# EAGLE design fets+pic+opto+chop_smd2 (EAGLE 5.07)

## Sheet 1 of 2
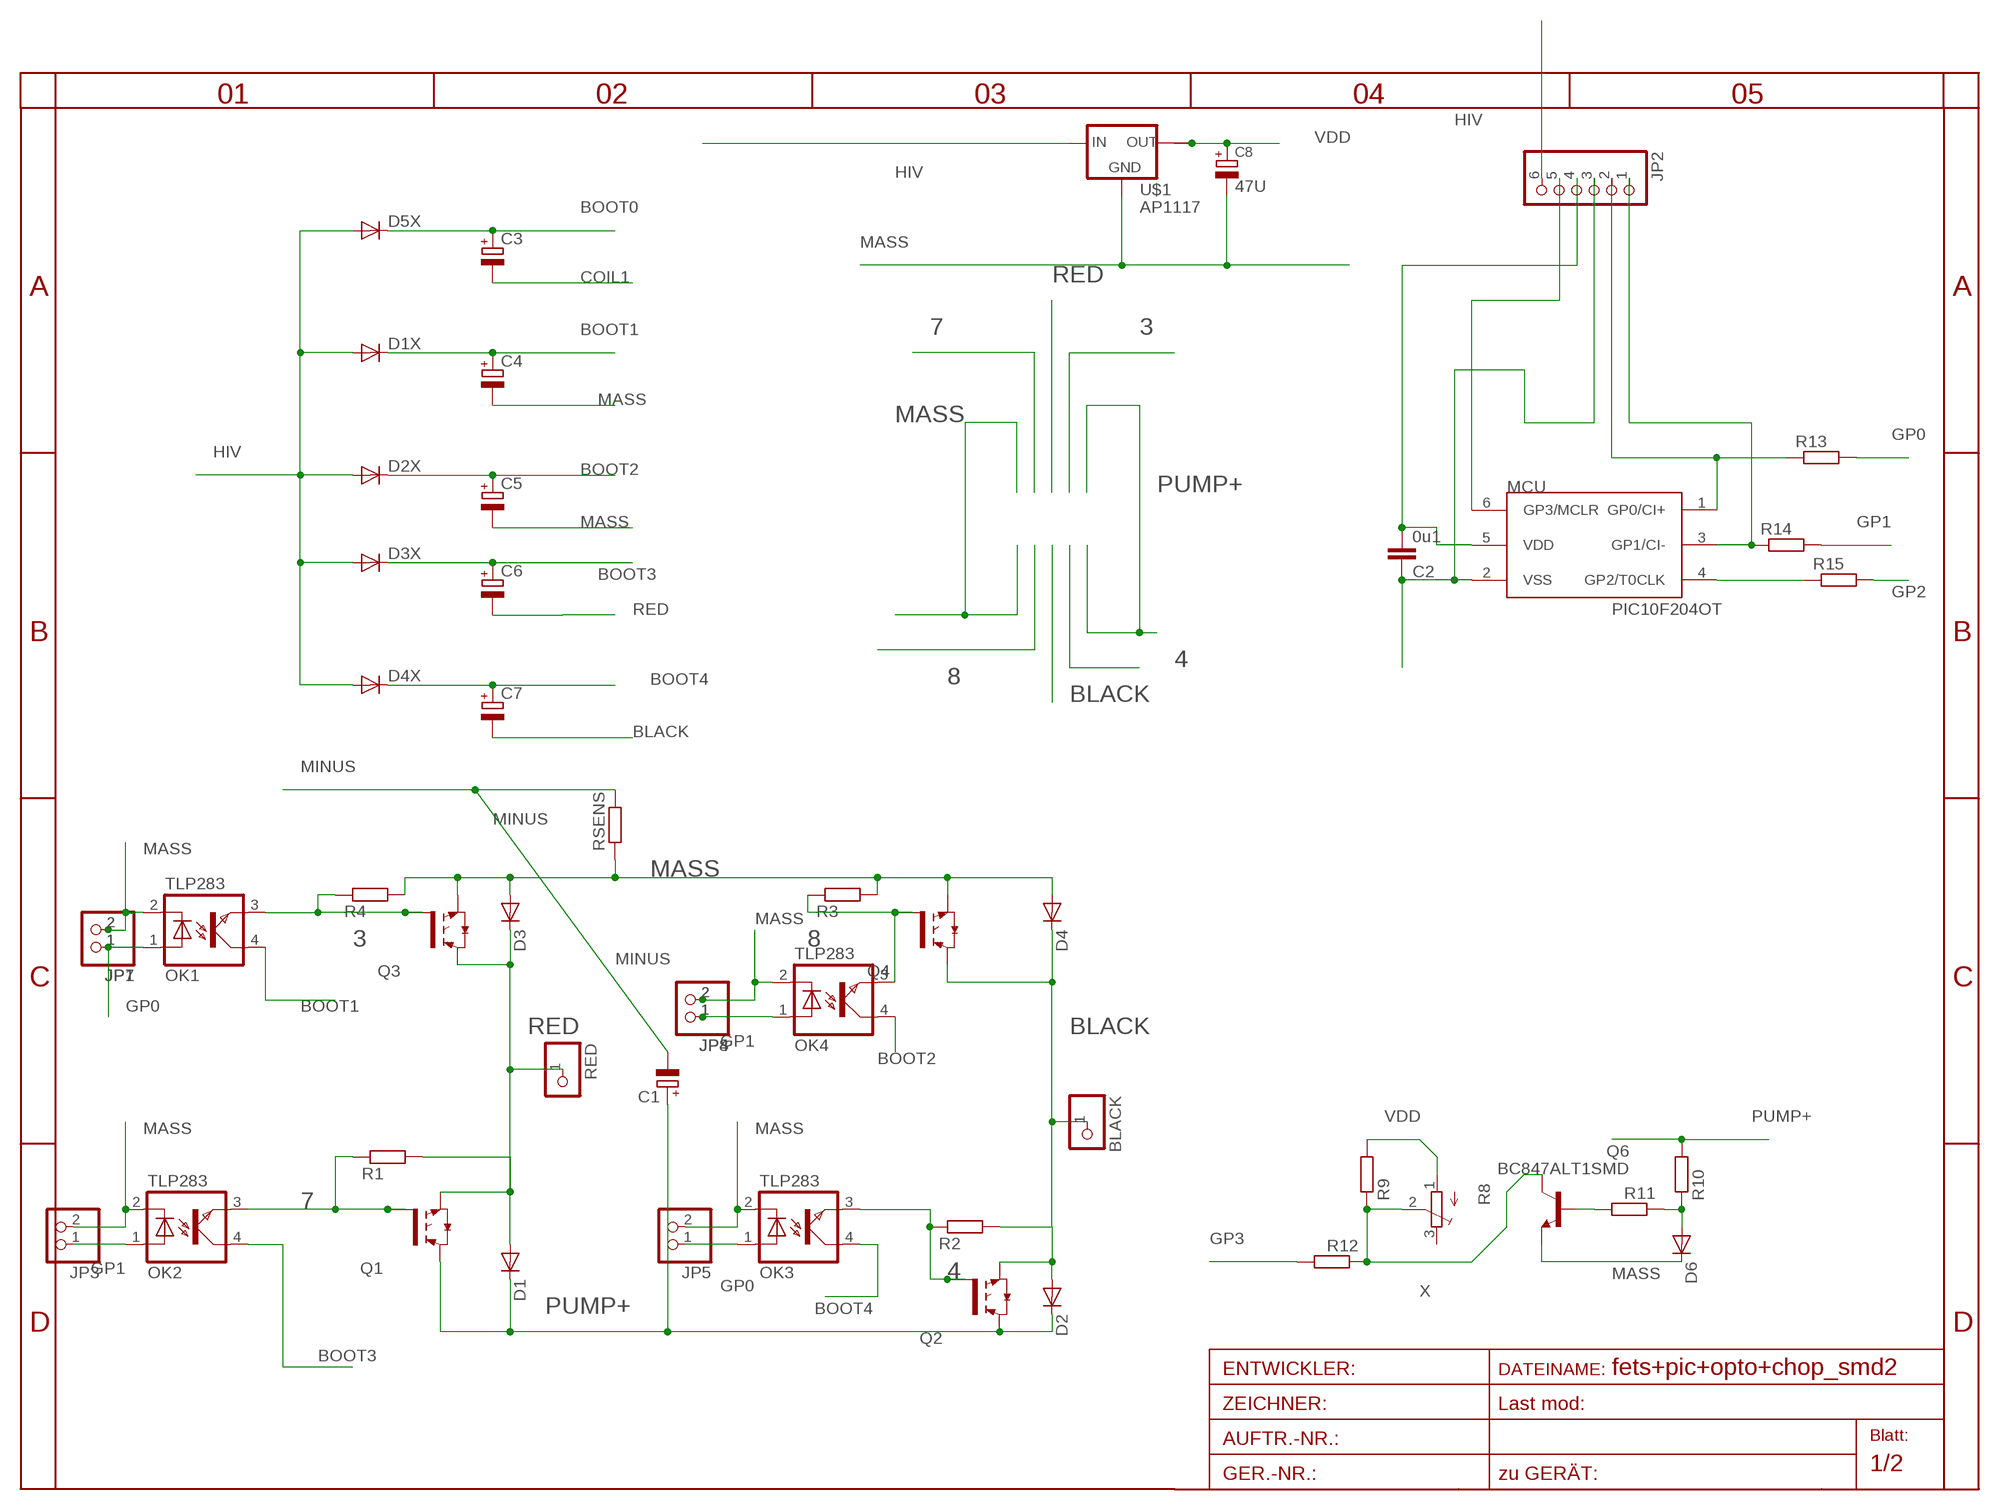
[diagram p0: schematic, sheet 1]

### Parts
BLACK  PINHD-1X14.5MM  [1X4MM5]
C1  CPOL-EUE5-13  [E5-13]
C2  0u1  C-EUC0805  [C0805]
C3  CPOL-EUC  [PANASONIC_C]
C4  CPOL-EUC  [PANASONIC_C]
C5  CPOL-EUC  [PANASONIC_C]
C6  CPOL-EUC  [PANASONIC_C]
C7  CPOL-EUC  [PANASONIC_C]
C8  47U  CPOL-EUC  [PANASONIC_C]
D1  DIODE-SMC  [SMC]
D1X  DIODE-SMA-DO214  [SMA-DO214AC]
D2  DIODE-SMC  [SMC]
D2X  DIODE-SMA-DO214  [SMA-DO214AC]
D3  DIODE-SMC  [SMC]
D3X  DIODE-SMA-DO214  [SMA-DO214AC]
D4  DIODE-SMC  [SMC]
D4X  DIODE-SMA-DO214  [SMA-DO214AC]
D5X  DIODE-SMA-DO214  [SMA-DO214AC]
D6  DIODE-MINIMELF  [MINIMELF]
JP1  PINHD-1X2STR  [1X02]
JP2  PINHD-1X6  [1X06BOX]
JP3  PINHD-1X2STR  [1X02]
JP4  PINHD-1X2STR  [1X02]
JP5  PINHD-1X2STR  [1X02]
JP7  PINHD-1X2STR  [1X02]
JP8  PINHD-1X2STR  [1X02]
MCU  PIC10F204OT  [SOT23-6]
OK1  TLP283  [MINI-FLAT-4]
OK2  TLP283  [MINI-FLAT-4]
OK3  TLP283  [MINI-FLAT-4]
OK4  TLP283  [MINI-FLAT-4]
Q1  IRG4BC15UD-S  [D2PACK]
Q2  IRG4BC15UD-S  [D2PACK]
Q3  IRG4BC15UD-S  [D2PACK]
Q4  IRG4BC15UD-S  [D2PACK]
Q6  BC847ALT1SMD  [SOT23]
R1  R-EU_R1206  [R1206]
R2  R-EU_R1206  [R1206]
R3  R-EU_R1206  [R1206]
R4  R-EU_R1206  [R1206]
R8  TRIM_EU-3223W  [3223W]
R9  R-EU_R1206  [R1206]
R10  R-EU_R1206  [R1206]
R11  R-EU_R1206  [R1206]
R12  R-EU_R1206  [R1206]
R13  R-EU_0207/25  [0207/25]
R14  R-EU_0207/25  [0207/25]
R15  R-EU_0207/25  [0207/25]
RED  PINHD-1X14.5MM  [1X4MM5]
RSENS  R-EU_CERAM50  [CERAM50]
U$1  AP1117  [SOT223]

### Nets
3: OK1.3(EMIT) Q3.1(G) R4.1
4: OK3.3(EMIT) Q2.1(G) R2.1
7: OK2.3(EMIT) Q1.1(G) R1.1
8: OK4.3(EMIT) Q4.1(G) R3.1
BLACK: BLACK.1 C7.- D2.A D4.C Q2.3(E) Q4.2(C) R2.2
BOOT0: C3.+ D5X.K(C) ; also sheet 2
BOOT1: C4.+ D1X.K(C) OK1.4(COL)
BOOT2: C5.+ D2X.K(C) OK4.4(COL)
BOOT3: C6.+ D3X.K(C) OK2.4(COL)
BOOT4: C7.+ D4X.K(C) OK3.4(COL)
COIL1: C3.- ; also sheet 2
GP0: JP1.1 JP5.1 JP7.1 OK1.1(A) OK3.1(A) R13.2
GP0I: JP2.2 MCU.1(GP0/CI+) R13.1
GP1: JP3.1 JP4.1 JP8.1 OK2.1(A) OK4.1(A) R14.2
GP1I: JP2.1 MCU.3(GP1/CI-) R14.1
GP2: R15.2 ; also sheet 2
GP2I: MCU.4(GP2/T0CLK) R15.1
GP3: JP2.5 MCU.6(GP3/MCLR) R12.2
HIV: D1X.A D2X.A D3X.A D4X.A D5X.A JP2.6 U$1.3(IN) ; also sheet 2
MASS: C2.1 C4.- C5.- C8.- D3.A D4.A D6.C JP1.2 JP2.3 JP3.2 JP4.2 JP5.2 JP7.2 JP8.2 MCU.2(VSS) OK1.2(C) OK2.2(C) OK3.2(C) OK4.2(C) Q3.3(E) Q4.3(E) Q6.2(E) R3.2 R4.2 RSENS.1 U$1.1(GND) ; also sheet 2
MINUS: C1.- RSENS.2 ; also sheet 2
N$4: D6.A R10.1 R11.1
N$5: Q6.1(B) R11.2
PUMP+: C1.+ D1.C D2.C Q1.2(C) Q2.2(C) R10.2 ; also sheet 2
RED: C6.- D1.A D3.C Q1.3(E) Q3.2(C) R1.2 RED.1
VDD: C2.2 C8.+ JP2.4 MCU.5(VDD) R8.1(A) R9.2 U$1.2(OUT) U$1.4(TAB)
X: Q6.3(C) R8.2(S) R9.1 R12.1
Unconnected: R8.3(E)

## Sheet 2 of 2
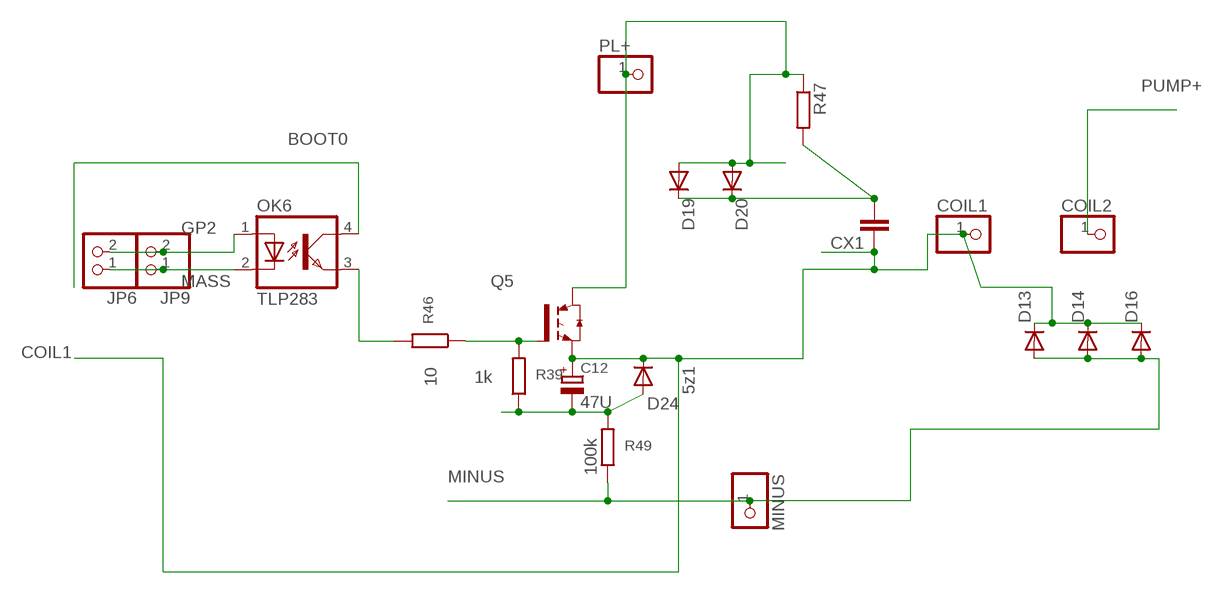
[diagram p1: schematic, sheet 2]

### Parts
C12  47U  CPOL-EUC  [PANASONIC_C]
COIL1  PINHD-1X14.5MM  [1X4MM5]
COIL2  PINHD-1X14.5MM  [1X4MM5]
CX1  CXXC22B10  [XC22B10]
D13  DIODE-SMC  [SMC]
D14  DIODE-SMC  [SMC]
D16  DIODE-SMC  [SMC]
D19  DIODE-SMC  [SMC]
D20  DIODE-SMC  [SMC]
D24  5z1  DIODE-MINIMELF  [MINIMELF]
JP6  PINHD-1X2STR  [1X02]
JP9  PINHD-1X2STR  [1X02]
MINUS  PINHD-1X14.5MM  [1X4MM5]
OK6  TLP283  [MINI-FLAT-4]
PL+  PINHD-1X14.5MM  [1X4MM5]
Q5  IRG4BC15UD-S  [D2PACK]
R39  1k  R-EU_R1206  [R1206]
R46  10  R-EU_R1206  [R1206]
R47  R-EU_0207/5V  [0207/5V]
R49  100k  R-EU_R1206  [R1206]

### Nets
BATT-: C12.- D24.A R39.1 R49.2
BOOT0: OK6.4(COL) ; also sheet 1
COIL1: C12.+ COIL1.1 CX1.1 D13.C D14.C D16.C D24.C Q5.3(E) ; also sheet 1
GP2: JP6.2 JP9.2 OK6.1(A) ; also sheet 1
HIV: D19.A D20.A PL+.1 Q5.2(C) R47.1 ; also sheet 1
MASS: JP6.1 JP9.1 OK6.2(C) ; also sheet 1
MINUS: D13.A D14.A D16.A MINUS.1 R49.1 ; also sheet 1
N$43: OK6.3(EMIT) R46.2
N$45: Q5.1(G) R39.2 R46.1
PUMP+: COIL2.1 ; also sheet 1
SNUB: CX1.2 D19.C D20.C R47.2

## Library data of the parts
BLACK COIL1 COIL2 MINUS PL+ RED = pinhead:PINHD-1X1: PIN HEADER
C1 C3-C7 = rcl:CPOL-EU: POLARIZED CAPACITOR, European symbol
C2 = rcl:C-EU: CAPACITOR, European symbol
C8 C12 = rcl-2:CPOL-EU: POLARIZED CAPACITOR, European symbol
CX1 = rcl:CX: X CAPACITOR
D1 D1X D2 D2X D3 D3X D4 D4X D5X D6 D13 D14 D16 D19 D20 D24 = diode:DIODE-: DIODE
JP1 JP3-JP9 = pinhead:PINHD-1X2: PIN HEADER
JP2 = pinhead:PINHD-1X6: PIN HEADER
MCU = microchip-3:PIC10F2*: uPC nW 0,25/0,5k Program Flash memory Comparator
OK1-OK4 OK6 = optocoupler:TLP283: TOSHIBA PHOTOCOUPLER GaAs IRED & PHOTO-TRANSISTOR Source: http://www.semicon.toshiba.co.jp/td/en/Opto/Photocoupler/en_20050928_TLP283_datasheet.pdf
Q1-Q5 = transistor-power:IRG4BC15UD-: INSULATED GATE BIPOLAR TRANSISTOR WITH ULTRAFAST SOFT RECOVERY DIODE
Q6 = transistor-npn:BC847*: NPN Transistor
R1-R4 R9-R12 R47 RSENS = rcl:R-EU_: RESISTOR, European symbol
R8 = pot:TRIM_EU-: POTENTIOMETER
R13-R15 R39 R46 R49 = rcl-2:R-EU_: RESISTOR, European symbol
U$1 = v-reg:AP1117

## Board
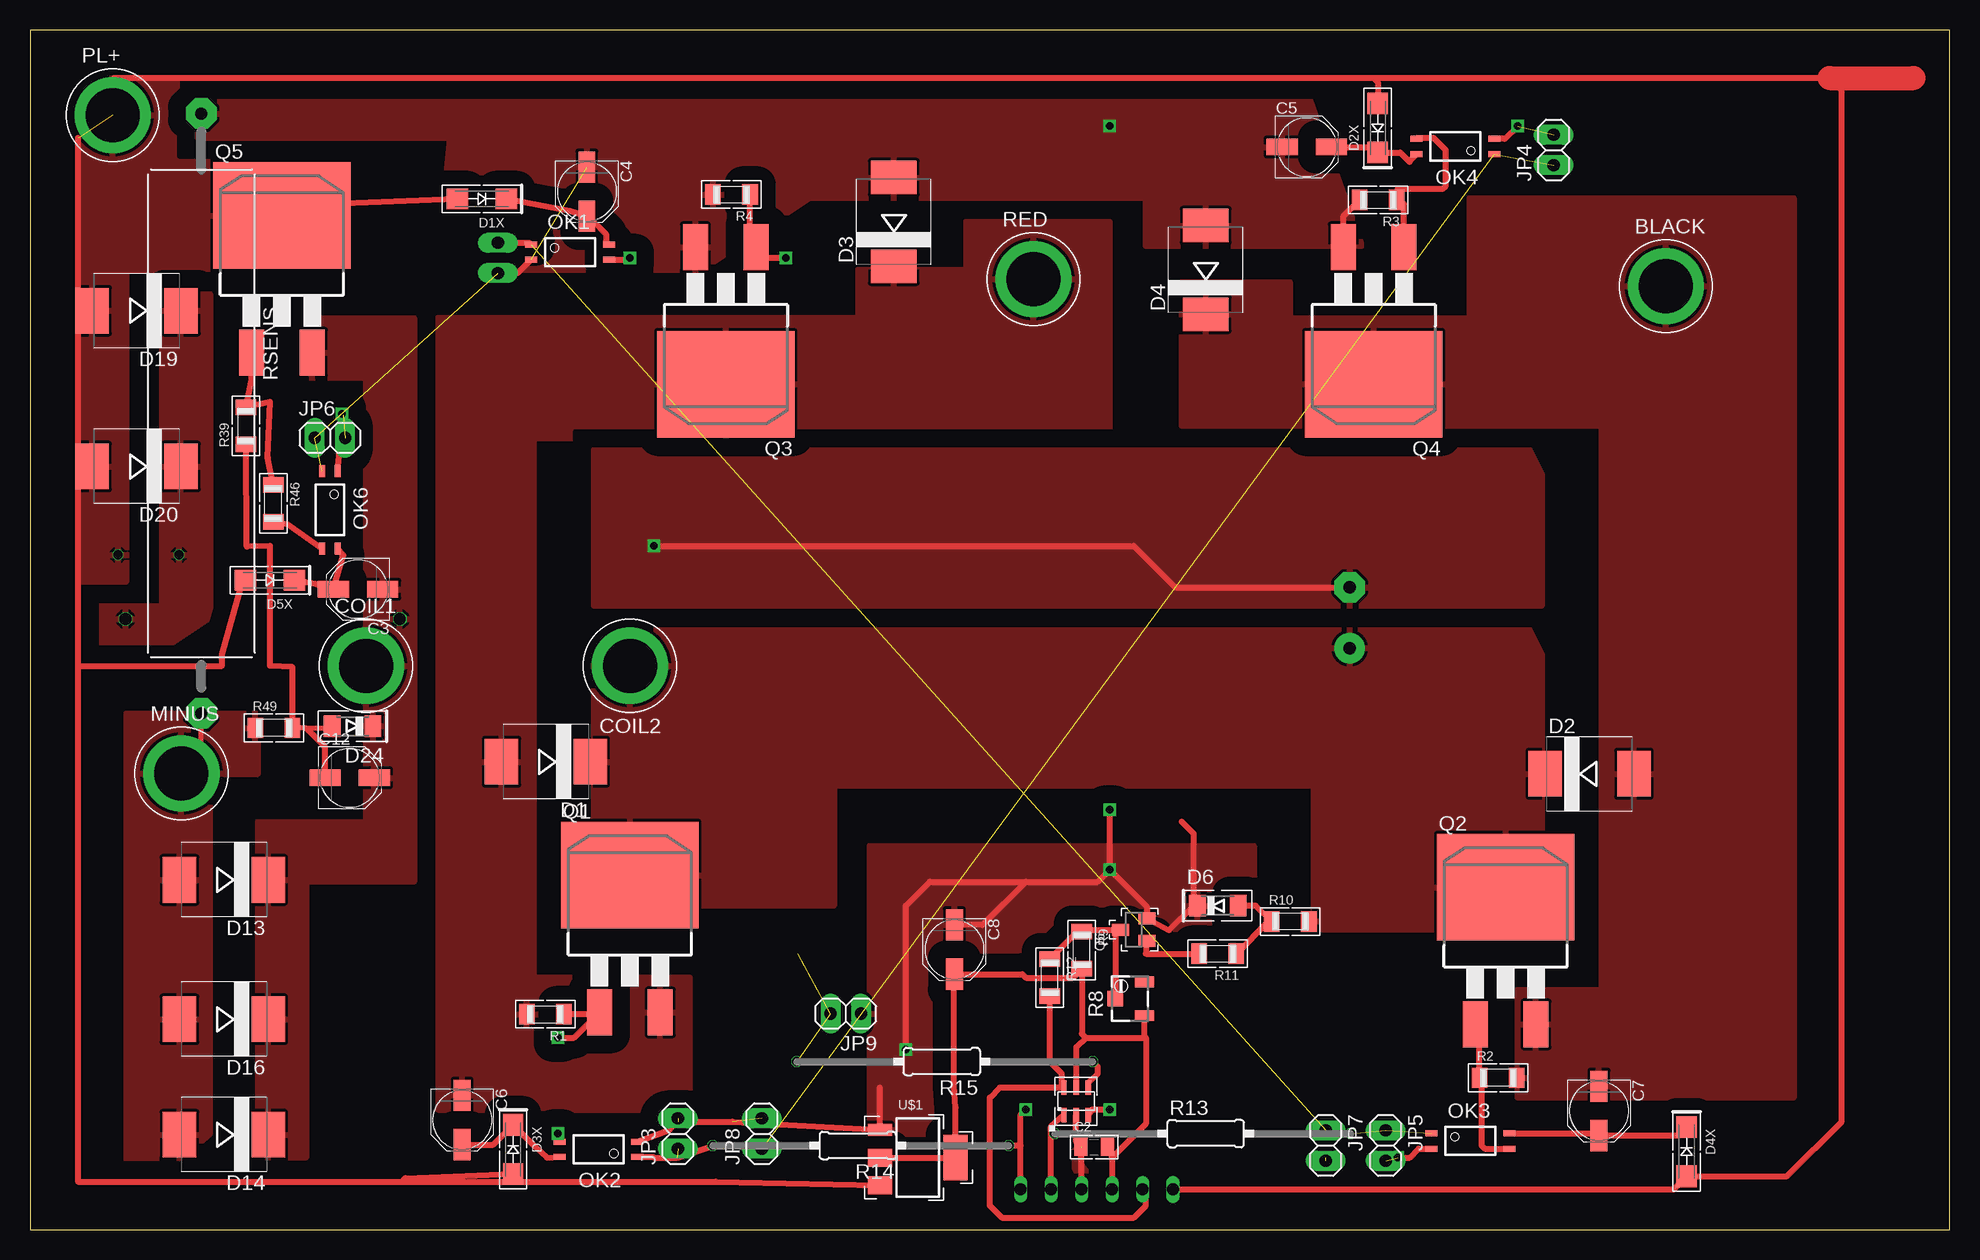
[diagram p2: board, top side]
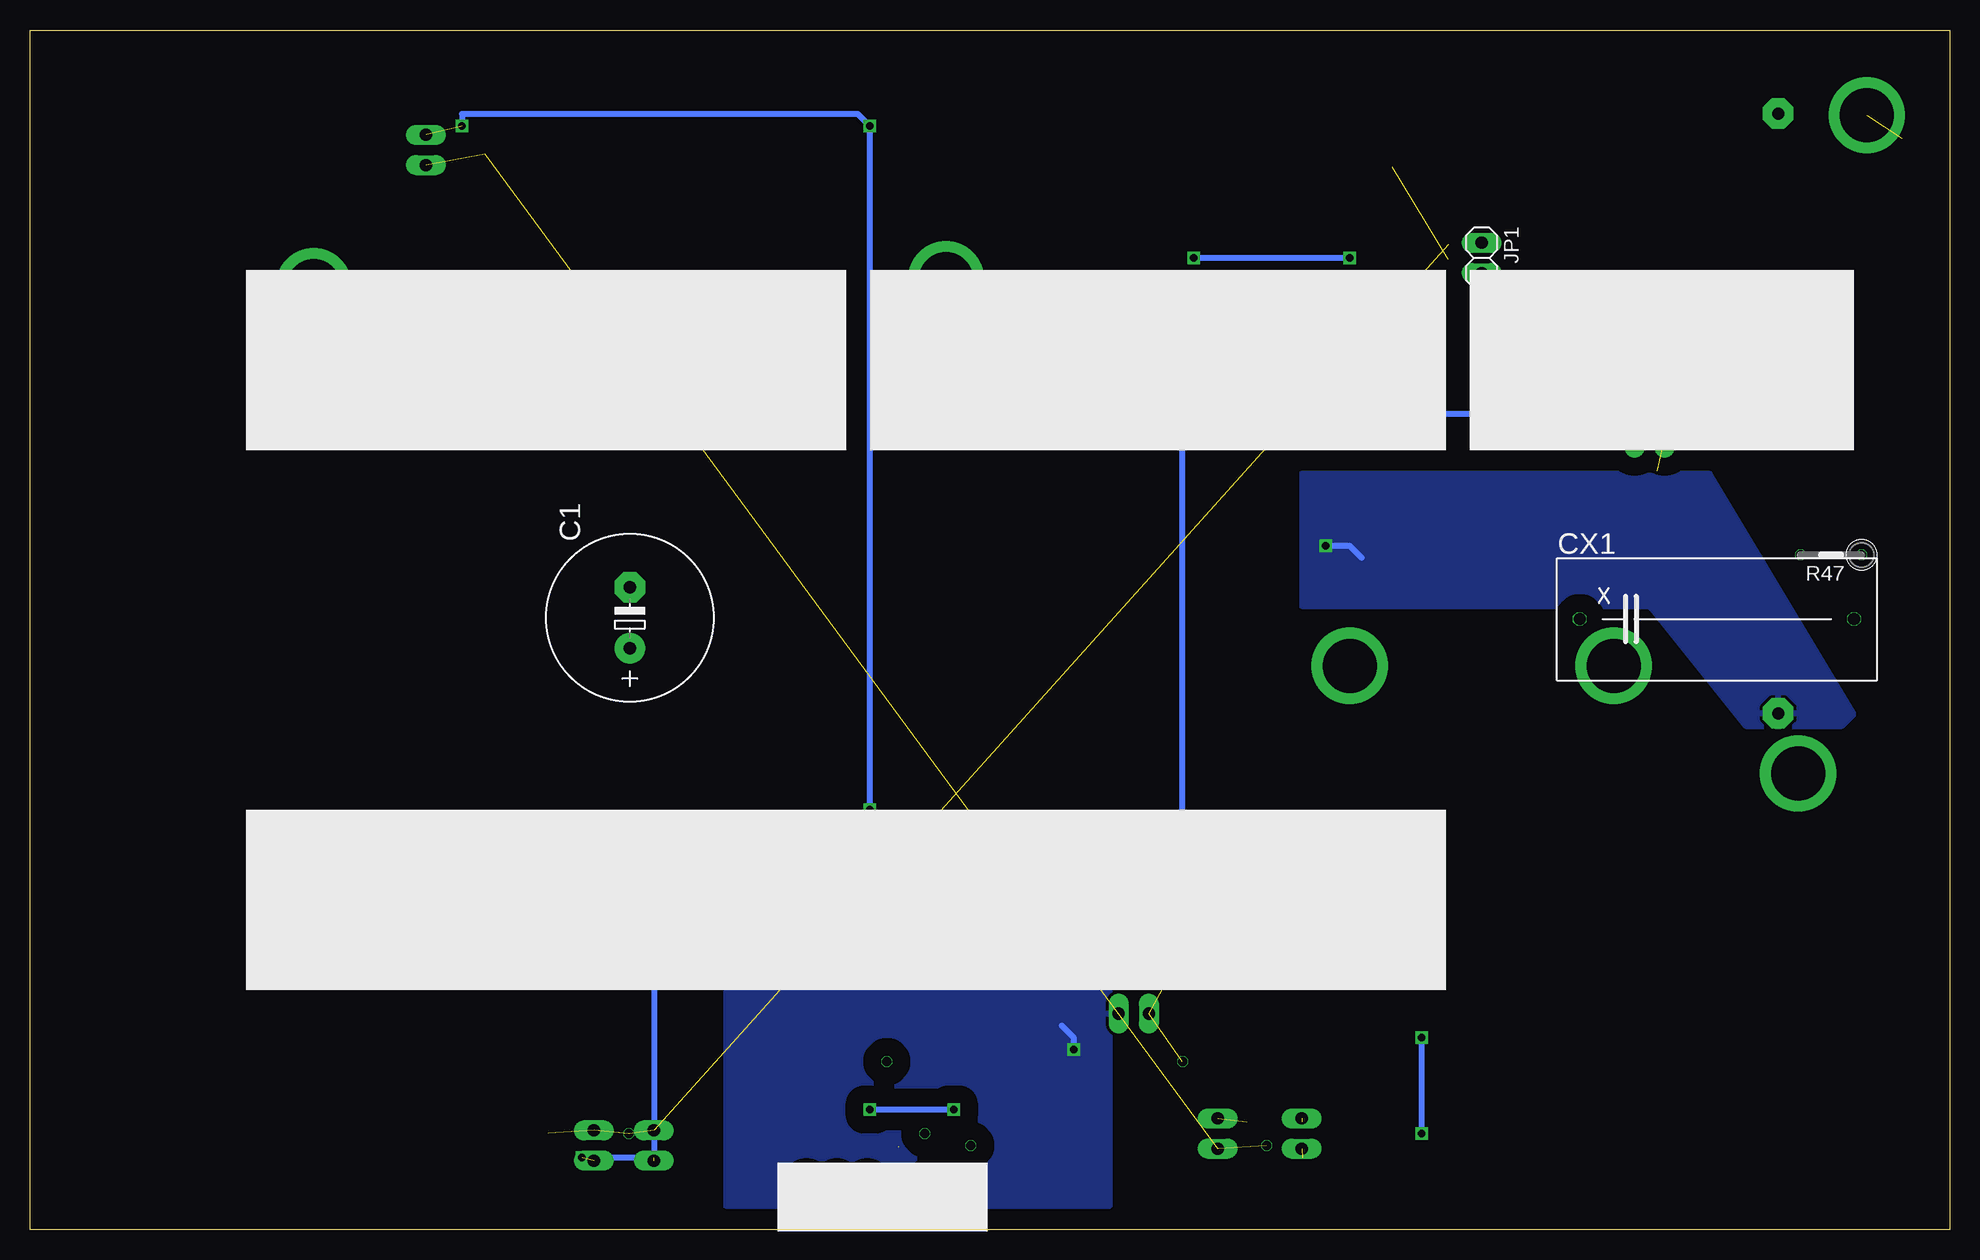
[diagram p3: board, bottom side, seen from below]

Size 160 x 100 mm. Coordinates in mm from the lower left corner, seen from the top.
Outline: 0,0 160,0 160,100 0,100 0,0
Copper layers (1*16): Top 0.035mm / dielectric 1.5mm / Bottom 0.035mm
Design rules "default": minimum track width 10mil, minimum drill 20mil, track to track 8mil, track to pad 8mil, pad to pad 8mil, via to via 8mil, smd to smd 8mil, copper to edge 40mil, drill to drill 8mil, minimum pad ring 1mil, minimum via ring 8mil, stop-mask expansion 4mil, vias tented up to drill 0mil, thermal gap 10mil

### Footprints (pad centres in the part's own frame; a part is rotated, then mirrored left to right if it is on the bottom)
1X4MM5 = drill 4.5 pad 6.35 round: 1 0,0
E5-13 = drill 1.016 pad 2.54 round: + -2.54,0 | drill 1.016 pad 2.54 octagon: - 2.54,0
C0805 = smd 1.1 x 1.5: 1 -1.1,0; 2 1.1,0
PANASONIC_C = smd 2.6 x 1.4: + 2.05,0; - -2.05,0
XC22B10 = drill 1.016 octagon: 1 -11.43,0.025; 2 11.43,0.025
SMC = smd 2.8 x 3.8: A 3.7,0; C -3.7,0
SMA-DO214AC = smd 1.8 x 1.7: A 2.05,-0.127; K -2.05,-0.127
MINIMELF = smd 1.4 x 1.8: A 1.7,0; C -1.7,0
1X02 = drill 1.016 pad 1.676 long: 1 -1.27,0; 2 1.27,0
1X06BOX = drill 1 long: 1 -6.35,0; 2 -3.81,0; 3 -1.27,0; 4 1.27,0; 5 3.81,0 | drill 1.016 long: 6 6.35,0
SOT23-6 = smd 0.45 x 1.2: 1 -1.016,-1.15; 2 0,-1.15; 3 1.016,-1.15; 4 1.016,1.15; 5 0,1.15; 6 -1.016,1.15
MINI-FLAT-4 = smd 1 x 0.5: 1 -3.24,0.635; 2 -3.24,-0.635; 3 3.24,-0.635; 4 3.24,0.635
D2PACK = smd 2.083 x 3.81: 1 -2.54,-8.89; 3 2.54,-8.89 | smd 11.43 x 8.89: 2 0,2.54
SOT23 = smd 1 x 1.4: 1 -0.95,-1.1; 2 0.95,-1.1; 3 0,1.1
R1206 = smd 1.3 x 1.7: 1 -1.55,0; 2 1.55,0
3223W = smd 0.9 x 1.6: 1 -1.4,-1.215; 3 1.4,-1.215 | smd 1.3 x 1.3: 2 0,1.215
0207/25 = drill 0.813 octagon: 1 -12.58,0; 2 12.08,0
0207/5V = drill 0.813 octagon: 1 -2.54,0; 2 2.54,0
CERAM50 = drill 1 pad 2.54 octagon: 1 -25,0; 2 25,0
SOT223 = smd 1 x 2: 1 -2.3,-3.15 | smd 1.5 x 2: 2 0,-3.15; 3 2.3,-3.15 | smd 3.8 x 2: 4 0,3.15

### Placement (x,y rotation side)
BLACK  136.35,78.64 0 top
C1  110,51 90 bottom
C2  88.7,6.88 0 top
C3  27.34,53.37 180 top
C4  46.42,86.52 270 top
C5  106.43,90.25 0 top
C6  36.02,9.13 270 top
C7  130.78,9.89 270 top
C8  77.05,23.34 270 top
C12  26.65,37.66 0 top
COIL1  28,47 0 top
COIL2  50,47 180 top
CX1  19.39,50.87 0 bottom
D1  43,39 180 top
D1X  37.66,85.79 180 top
D2  130,38 0 top
D2X  112.22,91.83 90 top
D3  72,84 90 top
D3X  40.4,6.68 270 top
D4  98,80 90 top
D4X  138.22,6.49 270 top
D5X  20,54 180 top
D6  99,27 0 top
D13  16.16,29.15 180 top
D14  16.16,7.91 180 top
D16  16.16,17.53 180 top
D19  8.88,76.59 180 top
D20  8.88,63.62 180 top
D24  26.89,41.96 180 top
JP1  39,81 270 bottom
JP2  88.93,3.35 180 bottom
JP3  54,8 90 top
JP4  127,90 90 top
JP5  113,7 270 top
JP6  25,66 0 top
JP7  108,7 270 top
JP8  61,8 90 top
JP9  68,18 180 top
MCU  87.2,10.7 0 top
MINUS  12.62,38.02 0 top
OK1  45.01,81.48 0 top
OK2  47.38,6.68 180 top
OK3  120.06,7.38 0 top
OK4  118.81,90.29 180 top
OK6  25,60 270 top
PL+  6.89,92.9 0 top
Q1  50,27 0 top
Q2  123,26 0 top
Q3  58,73 180 top
Q4  112,73 180 top
Q5  21,82 0 top
Q6  92,25 90 top
R1  42.95,17.95 180 top
R2  122.38,12.65 0 top
R3  112.38,85.83 180 top
R4  58.47,86.29 180 top
R8  91.68,19.24 90 top
R9  87.67,23.3 270 top
R10  105.05,25.67 0 top
R11  99,23 180 top
R12  85,21 270 top
R13  98,8 0 top
R14  69,7 180 top
R15  76,14 180 top
R39  18,67 90 top
R46  20.28,60.54 270 top
R47  9.88,56.24 180 bottom
R49  20.34,41.81 0 top
RED  83.65,79.23 0 top
RSENS  14.29,68.04 270 top
U$1  74,6 270 top

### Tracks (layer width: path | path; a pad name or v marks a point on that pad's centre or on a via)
3  (via drill 0.6)
  Top 0.5: OK1.3 49.84,80.84 v50,81 | v63,81 61.43,81 Q3.1 60.02,82.41 R4.1
  Bottom 0.5: v50,81 v63,81
4
  Top 0.5: OK3.3 121.25,6.75 121,7 121,12.48 R2.1 120.83,15.83 121,16 121,16.57 Q2.1
7  (via drill 0.6)
  Top 0.5: OK2.3 44.14,8.14 v44,8 | v44,16 45.35,16 Q1.1 47.3,17.95 R1.1
  Bottom 0.5: v44,8 v44,16
8
  Top 0.5: Q4.1 114.54,85.46 114,86 114,86.76 | 114,86.76 R3.1 | 114,86.76 117.76,86.76 118,87 118,90 117,91 115.64,91 OK4.3
BATT-
  Top 0.406: R49.2 23,41.81 25.04,41.81 D24.A
  Top 0.5: R49.2 21.89,46.89 20,47 20,57 18.08,56.92 R39.1 | C12.- 24.6,40.21 23,41.81
BLACK
  pour Top (isolate 1.5, rank 2): 96,79 105,79 105,76 120,76 120,86 147,86 147,11 124,11 124,20 131,20 131,67 96,67
BOOT0
  Top 0.5: D5X.K 23.76,53.84 C3.+ 26.11,56.2 OK6.4
BOOT1
  Top 0.5: D1X.K 44.97,84.92 C4.+ 47.53,83.47 48,83 48,82.36 OK1.4
BOOT2
  Top 0.5: C5.+ 111.88,90.25 D2X.K 114.22,89.78 115,89 115,89.08 OK4.4
BOOT3
  Top 0.5: C6.+ 38.62,7.08 D3X.K 42,7 43.09,6 OK2.4
BOOT4
  Top 0.5: D4X.K 137.39,7.84 C7.+ 130.6,8.02 OK3.4
COIL1
  pour Top (isolate 1.5, rank 2): 24,76 32,76 32,29 23,29 23,6 19,6 19,34 28,34 28,71 23,71 24,72
GP0  (4 unrouted)
  Top 0.5: JP1.1 41.62,82.27 OK1.1
GP0I
  Top 0.5: JP2.2 85.12,8 | 85.12,8 85.12,8.62 MCU.1 | 85.12,8 R13.1
GP1  (4 unrouted)
  Top 0.5: OK2.1 51.95,6.04 52,6 53.92,6 R14.2
GP1I  (via drill 0.6)
  Top 0.5: JP2.1 82.58,7 | 82.58,7 82.58,9.58 v83,10 | v90,10 88.53,10 MCU.3 | 82.58,7 R14.1
  Bottom 0.5: v83,10 v90,10
GP2  (via drill 0.6)  (3 unrouted)
  Top 0.5: OK6.1 26.11,67.89 v26,68
  Bottom 0.5: v26,68 61,68 64,65 64,23
GP2I
  Top 0.5: MCU.4 88.22,12.22 89,13 89,13.58 R15.1
GP3
  Top 0.5: R12.2 85,14 86,13 86,11.9 MCU.6 80.85,11.85 80,11 80,2 81,1 92,1 93,2 93,3.09 JP2.5
HIV  (1 unrouted)
  Top 0.5: 112,96 150,96 151,95 151,9 146.44,4.44 D4X.A 137,3.35 JP2.6 | 112,96 7,96 | 4,47 4,4 31,4 | 4,47 4,91 | 31,4 57.15,4 U$1.3 | D3X.A 31.27,4.27 31,4 | D1X.A 21.85,85.39 Q5.2 | D5X.A 17.61,53.61 16,48 16,47 4,47 | D2X.A 112.35,95.65 112,96
  Top 2: 150,96 157,96
  pour Top (isolate 1.5, rank 2): 4,96 17,96 17,80 8,80 8,54 4,54
MASS  (via drill 0.6)  (9 unrouted)
  Top 0.5: JP2.3 87.66,6.84 87.2,7.3 MCU.2 | 70.85,11.85 U$1.1 58.55,9 54,9 53.31,8.31 OK2.2 | 96,34 97,33 97,27.3 D6.C 97,27 94.95,24.95 Q6.2 93.1,26.9 v90,30 | OK4.2 122.92,90.92 v124,92 | v90,30 v90,35 | OK3.2 115.75,6.75 115,6 v114,6 | C8.- 79.39,25.39 83,29 | 83,29 89,29 v90,30 | Q4.3 109.46,84.46 R3.2 | v73,15 73,27 75,29 83,29 | JP1.2 40.66,79.73 OK1.2
  Bottom 0.5: v90,35 v90,92 91,93 124,93 v124,92 | v73,15 73,16 74,17 | 90,29 v90,30 107,30 108,29 108,6 v114,6
  pour Top (isolate 1.5): 14,95 106,96 111,82 93,82 93,86 65,86 56,80 38,80 34,81 35,91 14,91
  pour Bottom (isolate 1.5, rank 2): 70,32 102,32 102,2 70,2
  pour Top (isolate 1.5, rank 2): 70,32 102,32 102,2 70,2
MINUS  (via drill 0.6)
  Top 0.406: RSENS.2 14.29,39.69 MINUS.1
  Top 0.5: C1.- 95.46,53.54 92,57 v52,57
  Bottom 0.5: v52,57 50,57 49,56
  pour Top (isolate 1.5): 126,52 47,52 47,65 125,65 126,63
  pour Top (isolate 1.5, rank 3): 8,43 8,2 15,8 15,38 19,38 19,43
  pour Bottom (isolate 1.5, rank 2): 8,43 20,63 54,63 54,52 25,52 17,42 9,42
N$4
  Top 0.5: R11.1 103.22,25.67 R10.1 102.17,27 D6.A
N$5
  Top 0.5: R11.2 93,23 93,23.95 Q6.1
N$43
  Top 0.5: OK6.3 21.46,58.81 R46.2
N$45
  Top 0.5: Q5.1 18.46,70.85 R39.2 20,69 19.82,64.37 R46.1
PUMP+
  pour Top (isolate 1.5): 126,48 126,25 107,25 107,37 67,37 67,27 47,27 47,50 125,50
RED
  pour Top (isolate 1.5, rank 2): 90,66 90,84 78,84 78,80 69,80 69,76 34,76 34,10 55,10 55,21 42,21 42,66
SNUB
  pour Top (isolate 1.5, rank 2): 11,78 15,78 15,51 9,47 5,47 5,52 11,52
VDD
  Top 0.5: U$1.2 U$1.4 77.15,10.15 77,12 77,21.24 C8.+ 82.71,21.29 83,21 86.92,21 R9.2 87.67,16.33 88,16 | 90.2,6 JP2.4 | 90.2,6 90.2,6.33 C2.2 | MCU.5 87.2,15.2 88,16 | 88,16 93,16 | 93,16 93,8.8 90.2,6 | R8.1 92.89,16.11 93,16
X
  Top 0.5: R8.2 90.47,24.57 Q6.3 87.82,25 R9.1 87.3,24.85 R12.1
